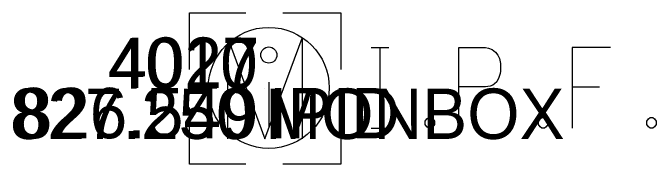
# Model space of a CAD drawing. Extents: x 1563429 to 1566163, y 633101 to 639596.
# Drawn here: x 1564700.03 to 1564712.79, y 637170.56 to 637173.57 of the extents above; entities that cross this region are included whole.
import ezdxf

# ---------------------------------------------------------------- set-up
doc = ezdxf.new("R2010")
doc.units = 0
for name, color, linetype in [('SV_X_Mon_Cells_Found', 7, 'Continuous'), ('SV_X_Text_Comment', 7, 'Continuous'), ('SV_X_Text_Elevation', 7, 'Continuous'), ('SV_X_Text_Name', 7, 'Continuous')]:
    doc.layers.add(name, color=color, linetype=linetype)

msp = doc.modelspace()

# ---------------------------------------------------------------- linework, layer by layer
at = {"layer": 'SV_X_Mon_Cells_Found'}
for p, q in [((1564705.104, 637172.194), (1564705.104, 637171.311)), ((1564705.028, 637172.064), (1564705.028, 637172.064))]:
    msp.add_line(p, q, dxfattribs=at)
for points in [[(1564703.528, 637172.443), (1564703.528, 637173.566), (1564704.651, 637173.566)], [(1564705.383, 637173.566), (1564706.53, 637173.566), (1564706.53, 637172.443)], [(1564704.288, 637171.064), (1564704.288, 637173.064), (1564705.028, 637171.064), (1564705.768, 637173.064), (1564705.768, 637171.064)], [(1564707.134, 637172.877), (1564707.487, 637172.877)], [(1564707.311, 637171.277), (1564707.311, 637172.877)], [(1564708.876, 637171.277), (1564708.876, 637172.877), (1564709.405, 637172.877), (1564709.46, 637172.865), (1564709.537, 637172.839), (1564709.571, 637172.814), (1564709.603, 637172.789), (1564709.648, 637172.726), (1564709.681, 637172.663), (1564709.703, 637172.562), (1564709.703, 637172.411), (1564709.692, 637172.361), (1564709.67, 637172.285), (1564709.626, 637172.197), (1564709.581, 637172.159), (1564709.548, 637172.134), (1564709.493, 637172.109), (1564709.405, 637172.096), (1564708.876, 637172.096)], [(1564711.885, 637172.877), (1564711.125, 637172.877), (1564711.125, 637171.277)], [(1564711.125, 637172.096), (1564711.665, 637172.096)], [(1564704.651, 637170.564), (1564703.528, 637170.564), (1564703.528, 637171.686)], [(1564706.53, 637171.686), (1564706.53, 637170.564), (1564705.383, 637170.564)], [(1564708.27, 637171.491), (1564708.325, 637171.491), (1564708.358, 637171.466), (1564708.391, 637171.416), (1564708.391, 637171.353), (1564708.358, 637171.302), (1564708.325, 637171.277), (1564708.27, 637171.277), (1564708.237, 637171.302), (1564708.204, 637171.353), (1564708.204, 637171.416), (1564708.237, 637171.466), (1564708.27, 637171.491)], [(1564710.518, 637171.491), (1564710.574, 637171.491), (1564710.607, 637171.466), (1564710.64, 637171.416), (1564710.64, 637171.353), (1564710.607, 637171.302), (1564710.574, 637171.277), (1564710.518, 637171.277), (1564710.485, 637171.302), (1564710.452, 637171.353), (1564710.452, 637171.416), (1564710.485, 637171.466), (1564710.518, 637171.491)], [(1564712.668, 637171.491), (1564712.723, 637171.491), (1564712.756, 637171.466), (1564712.789, 637171.416), (1564712.789, 637171.353), (1564712.756, 637171.302), (1564712.723, 637171.277), (1564712.668, 637171.277), (1564712.635, 637171.302), (1564712.602, 637171.353), (1564712.602, 637171.416), (1564712.635, 637171.466), (1564712.668, 637171.491)], [(1564707.134, 637171.277), (1564707.487, 637171.277)]]:
    msp.add_lwpolyline(points, dxfattribs=at)
for centre, radius in [((1564705.104, 637172.077), 1.2), ((1564705.104, 637172.729), 0.16)]:
    msp.add_circle(centre, radius, dxfattribs=at)

# ---------------------------------------------------------------- texts
at = {"layer": 'SV_X_Text_Comment'}
for s, p in [('MONBOX', (1564705.028, 637171.064)), ('IPID', (1564705.104, 637171.077))]:
    msp.add_text(s, height=1, dxfattribs=at).set_placement(p)
at = {"layer": 'SV_X_Text_Elevation'}
for s, p in [('827.250', (1564699.967, 637171.064)), ('826.549', (1564700.063, 637171.077))]:
    msp.add_text(s, height=1, dxfattribs=at).set_placement(p)
at = {"layer": 'SV_X_Text_Name'}
for s, p in [('4010', (1564701.908, 637172.064)), ('4027', (1564701.942, 637172.077))]:
    msp.add_text(s, height=1, dxfattribs=at).set_placement(p)

doc.saveas('drawing.dxf')
